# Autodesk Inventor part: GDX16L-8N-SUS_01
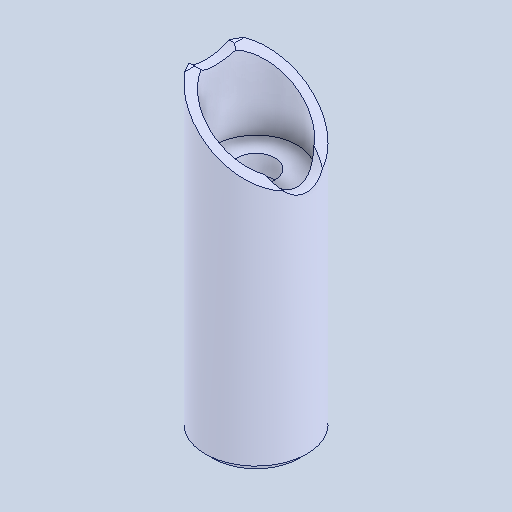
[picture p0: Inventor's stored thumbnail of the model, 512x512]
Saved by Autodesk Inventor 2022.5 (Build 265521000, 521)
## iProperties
Created: 2024-06
Part Number: GDX16L-8N-SUS_01
Material: 一般
Document SubType Name: Modeling
Designer: ImaoCorp
Density: 1 g/cm^3
Appearance: 既定
Author: ImaoCorp
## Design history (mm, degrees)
feature "GDX16L-8N-SUS_01"
node "ソリッド1"
